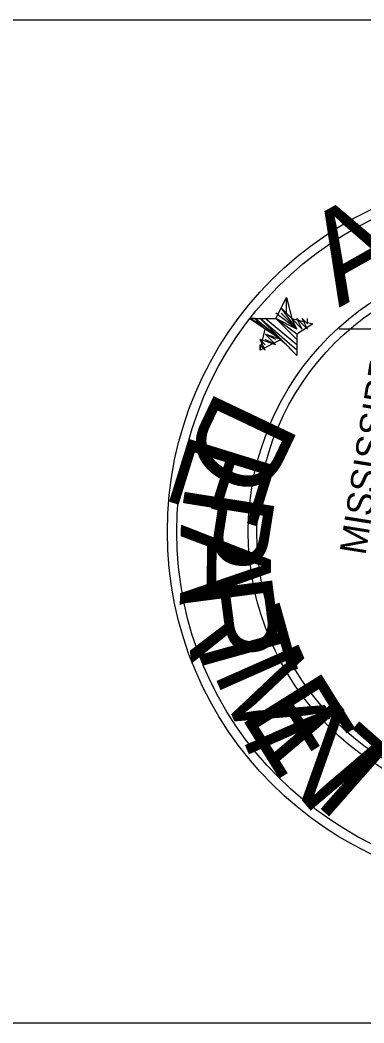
# Model space of a CAD drawing. Extents: x 1539684 to 1543084, y 305681 to 307881.
# Drawn here: x 1542601.8 to 1542635.9, y 305981.8 to 306081.3 of the extents above; entities that cross this region are included whole.
import ezdxf

# ---------------------------------------------------------------- set-up
doc = ezdxf.new("R2010")
doc.units = 0
for name, color, linetype in [('Default', 7, 'Continuous'), ('Level 1', 7, 'Continuous'), ('Level 3', 7, 'Continuous'), ('Level 5', 7, 'Continuous')]:
    doc.layers.add(name, color=color, linetype=linetype)

msp = doc.modelspace()

# ---------------------------------------------------------------- linework, layer by layer
at = {"layer": 'Default'}
for radius in [35.356, 34.425, 27.324, 26.481]:
    msp.add_circle((1542651.78, 306030.524), radius, dxfattribs=at)
at = {"layer": 'Level 1'}
msp.add_line((1542640.272, 306050.627), (1542633.465, 306050.627), dxfattribs=at)
at = {"layer": 'Level 3'}
for points in [[(1543034.351, 306081.267), (1542351.77, 306081.267)], [(1542583.82, 305981.817), (1543034.351, 305981.817)]]:
    msp.add_lwpolyline(points, dxfattribs=at)
at = {"layer": 'Level 5'}
for p, q in [((1542627.189, 306051.675), (1542628.237, 306053.765)), ((1542628.237, 306053.765), (1542628.761, 306051.675)), ((1542626.141, 306050.627), (1542624.575, 306051.675)), ((1542624.575, 306051.675), (1542627.189, 306051.675)), ((1542628.761, 306051.675), (1542630.851, 306051.151)), ((1542625.623, 306048.537), (1542626.141, 306050.627)), ((1542630.851, 306051.151), (1542629.278, 306050.11)), ((1542627.713, 306049.578), (1542625.623, 306048.537)), ((1542629.278, 306048.013), (1542627.713, 306049.578)), ((1542629.278, 306050.11), (1542629.278, 306048.013))]:
    msp.add_line(p, q, dxfattribs=at)
for points in [[(1542628.237, 306053.248), (1542628.237, 306053.765)], [(1542628.237, 306053.248), (1542628.237, 306053.765)], [(1542628.237, 306053.765), (1542628.237, 306053.765)], [(1542629.278, 306050.627), (1542627.713, 306052.723)], [(1542629.278, 306050.627), (1542627.713, 306052.723)], [(1542628.761, 306051.675), (1542627.713, 306052.723)], [(1542628.761, 306051.675), (1542627.713, 306052.723)], [(1542628.761, 306051.675), (1542627.713, 306052.723)], [(1542628.761, 306051.675), (1542627.713, 306052.723)], [(1542628.761, 306051.675), (1542627.713, 306052.723)], [(1542628.237, 306052.199), (1542627.713, 306052.723)], [(1542628.237, 306052.199), (1542627.713, 306052.723)], [(1542628.237, 306052.199), (1542627.713, 306052.723)], [(1542628.237, 306052.723), (1542628.237, 306053.248)], [(1542628.237, 306052.723), (1542628.237, 306053.248)], [(1542628.237, 306052.723), (1542628.237, 306053.248)], [(1542628.237, 306052.723), (1542628.237, 306053.248)], [(1542628.237, 306052.723), (1542628.237, 306053.248)], [(1542628.237, 306053.248), (1542628.237, 306053.248)], [(1542628.237, 306053.248), (1542628.237, 306053.248)], [(1542628.237, 306052.199), (1542628.237, 306052.723)], [(1542628.237, 306052.723), (1542628.237, 306052.723)], [(1542625.092, 306051.675), (1542624.575, 306051.675)], [(1542625.623, 306051.151), (1542624.575, 306051.675)], [(1542626.141, 306050.627), (1542625.092, 306051.675)], [(1542627.713, 306049.578), (1542625.092, 306051.675)], [(1542627.713, 306049.578), (1542625.092, 306051.675)], [(1542628.237, 306049.061), (1542625.092, 306051.675)], [(1542628.761, 306048.537), (1542625.623, 306051.675)], [(1542629.278, 306048.537), (1542625.623, 306051.675)], [(1542629.278, 306048.537), (1542625.623, 306051.675)], [(1542629.278, 306048.537), (1542625.623, 306051.675)], [(1542629.278, 306048.537), (1542625.623, 306051.675)], [(1542629.278, 306048.537), (1542625.623, 306051.675)], [(1542629.278, 306048.537), (1542625.623, 306051.675)], [(1542629.278, 306048.537), (1542625.623, 306051.675)], [(1542629.278, 306048.537), (1542625.623, 306051.675)], [(1542629.278, 306049.061), (1542626.141, 306051.675)], [(1542629.278, 306049.061), (1542626.141, 306051.675)], [(1542629.278, 306049.061), (1542626.141, 306051.675)], [(1542629.278, 306049.061), (1542626.141, 306051.675)], [(1542629.278, 306050.627), (1542627.189, 306052.199)], [(1542629.278, 306050.627), (1542627.189, 306052.199)], [(1542629.278, 306049.578), (1542627.189, 306051.675)], [(1542629.278, 306049.578), (1542627.189, 306051.675)], [(1542629.278, 306049.578), (1542627.189, 306051.675)], [(1542629.278, 306049.578), (1542627.189, 306051.675)], [(1542629.278, 306049.578), (1542627.189, 306051.675)], [(1542629.278, 306049.578), (1542627.189, 306051.675)], [(1542629.278, 306050.11), (1542627.189, 306051.675)], [(1542629.278, 306050.11), (1542627.189, 306051.675)], [(1542629.278, 306050.11), (1542627.189, 306051.675)], [(1542629.278, 306050.11), (1542627.189, 306051.675)], [(1542629.278, 306050.11), (1542627.189, 306051.675)], [(1542629.278, 306050.627), (1542627.189, 306051.675)], [(1542629.278, 306050.627), (1542627.713, 306052.199)], [(1542629.278, 306050.627), (1542627.713, 306052.199)], [(1542629.278, 306050.627), (1542627.713, 306052.199)], [(1542629.278, 306050.627), (1542627.713, 306052.199)], [(1542629.278, 306050.627), (1542627.713, 306052.199)], [(1542629.278, 306050.627), (1542628.761, 306051.675)], [(1542629.81, 306050.627), (1542628.761, 306051.675)], [(1542629.81, 306050.627), (1542628.761, 306051.675)], [(1542629.81, 306050.627), (1542629.278, 306051.675)], [(1542629.81, 306050.627), (1542629.278, 306051.675)], [(1542629.81, 306050.627), (1542629.278, 306051.675)], [(1542629.81, 306050.627), (1542629.278, 306051.675)], [(1542629.81, 306050.627), (1542629.278, 306051.675)], [(1542629.81, 306050.627), (1542629.278, 306051.675)], [(1542630.327, 306050.627), (1542629.278, 306051.675)], [(1542630.327, 306050.627), (1542629.278, 306051.675)], [(1542630.327, 306050.627), (1542629.81, 306051.675)], [(1542630.327, 306051.151), (1542629.81, 306051.675)], [(1542630.327, 306051.151), (1542629.81, 306051.675)], [(1542630.327, 306051.151), (1542629.81, 306051.675)], [(1542630.327, 306051.151), (1542630.327, 306051.675)], [(1542630.327, 306051.151), (1542630.327, 306051.675)], [(1542630.327, 306051.151), (1542630.327, 306051.675)], [(1542630.327, 306051.151), (1542630.327, 306051.675)], [(1542630.327, 306051.151), (1542630.327, 306051.675)], [(1542630.327, 306051.151), (1542630.327, 306051.675)], [(1542630.327, 306051.151), (1542630.327, 306051.675)], [(1542630.327, 306051.151), (1542630.327, 306051.675)], [(1542627.713, 306049.578), (1542626.141, 306050.627)], [(1542627.713, 306049.578), (1542626.141, 306050.627)], [(1542630.851, 306051.151), (1542630.851, 306051.151)], [(1542626.141, 306048.537), (1542625.623, 306049.578)], [(1542626.141, 306049.061), (1542625.623, 306049.578)], [(1542627.189, 306049.061), (1542625.623, 306049.578)], [(1542627.189, 306049.061), (1542625.623, 306049.578)], [(1542627.189, 306049.061), (1542625.623, 306049.578)], [(1542627.189, 306049.061), (1542625.623, 306049.578)], [(1542627.189, 306049.061), (1542626.141, 306050.11)], [(1542627.189, 306049.061), (1542626.141, 306050.11)], [(1542627.189, 306049.578), (1542626.141, 306050.11)], [(1542627.713, 306049.578), (1542626.141, 306050.11)], [(1542627.713, 306049.578), (1542626.141, 306050.11)], [(1542627.713, 306049.578), (1542626.141, 306050.11)], [(1542627.713, 306049.578), (1542626.141, 306050.11)], [(1542627.189, 306049.061), (1542626.141, 306049.578)], [(1542627.189, 306049.061), (1542626.141, 306049.578)], [(1542627.189, 306049.061), (1542626.141, 306049.578)], [(1542627.189, 306049.061), (1542626.141, 306049.578)], [(1542627.189, 306049.061), (1542626.141, 306049.578)], [(1542627.189, 306049.061), (1542626.141, 306049.578)], [(1542625.623, 306048.537), (1542625.623, 306049.061)], [(1542625.623, 306048.537), (1542625.623, 306049.061)], [(1542626.141, 306048.537), (1542625.623, 306049.061)], [(1542626.141, 306048.537), (1542625.623, 306049.061)], [(1542626.141, 306048.537), (1542625.623, 306049.061)], [(1542626.141, 306048.537), (1542625.623, 306049.061)], [(1542626.141, 306048.537), (1542625.623, 306049.061)], [(1542625.623, 306048.537), (1542625.623, 306048.537)], [(1542625.623, 306048.537), (1542625.623, 306048.537)], [(1542625.623, 306048.537), (1542625.623, 306048.537)], [(1542625.623, 306048.537), (1542625.623, 306048.537)], [(1542625.623, 306048.537), (1542625.623, 306048.537)], [(1542625.623, 306048.537), (1542625.623, 306048.537)], [(1542625.623, 306048.537), (1542625.623, 306048.537)], [(1542625.623, 306048.537), (1542625.623, 306048.537)]]:
    msp.add_lwpolyline(points, dxfattribs=at)

# ---------------------------------------------------------------- texts
at = {"layer": 'Level 1'}
msp.add_text('MISSISSIPPI', height=2.61507, rotation=80.94797, dxfattribs=at).set_placement((1542636.086, 306028.13))
at = {"layer": 'Level 5'}
for s, height, rotation, p in [('A', 9.073, 29.35935, (1542633.465, 306052.723)), ('D', 9.016, 244.57151, (1542621.437, 306044.875)), ('E', 9.007, 252.79594, (1542618.816, 306040.689)), ('P', 9.001, 261.00622, (1542618.299, 306035.454)), ('A', 8.997, 269.20879, (1542617.768, 306031.268)), ('R', 9.001, 277.41067, (1542617.768, 306025.509)), ('T', 9.004, 285.61894, (1542618.816, 306021.323)), ('M', 8.894, 293.84019, (1542620.906, 306016.62)), ('E', 9.023, 302.07997, (1542623.527, 306012.433)), ('N', 9.038, 310.34238, (1542625.623, 306008.771)), ('T', 9.051, 318.62966, (1542629.278, 306005.109))]:
    msp.add_text(s, height=height, rotation=rotation, dxfattribs=at).set_placement(p)

doc.saveas('drawing.dxf')
